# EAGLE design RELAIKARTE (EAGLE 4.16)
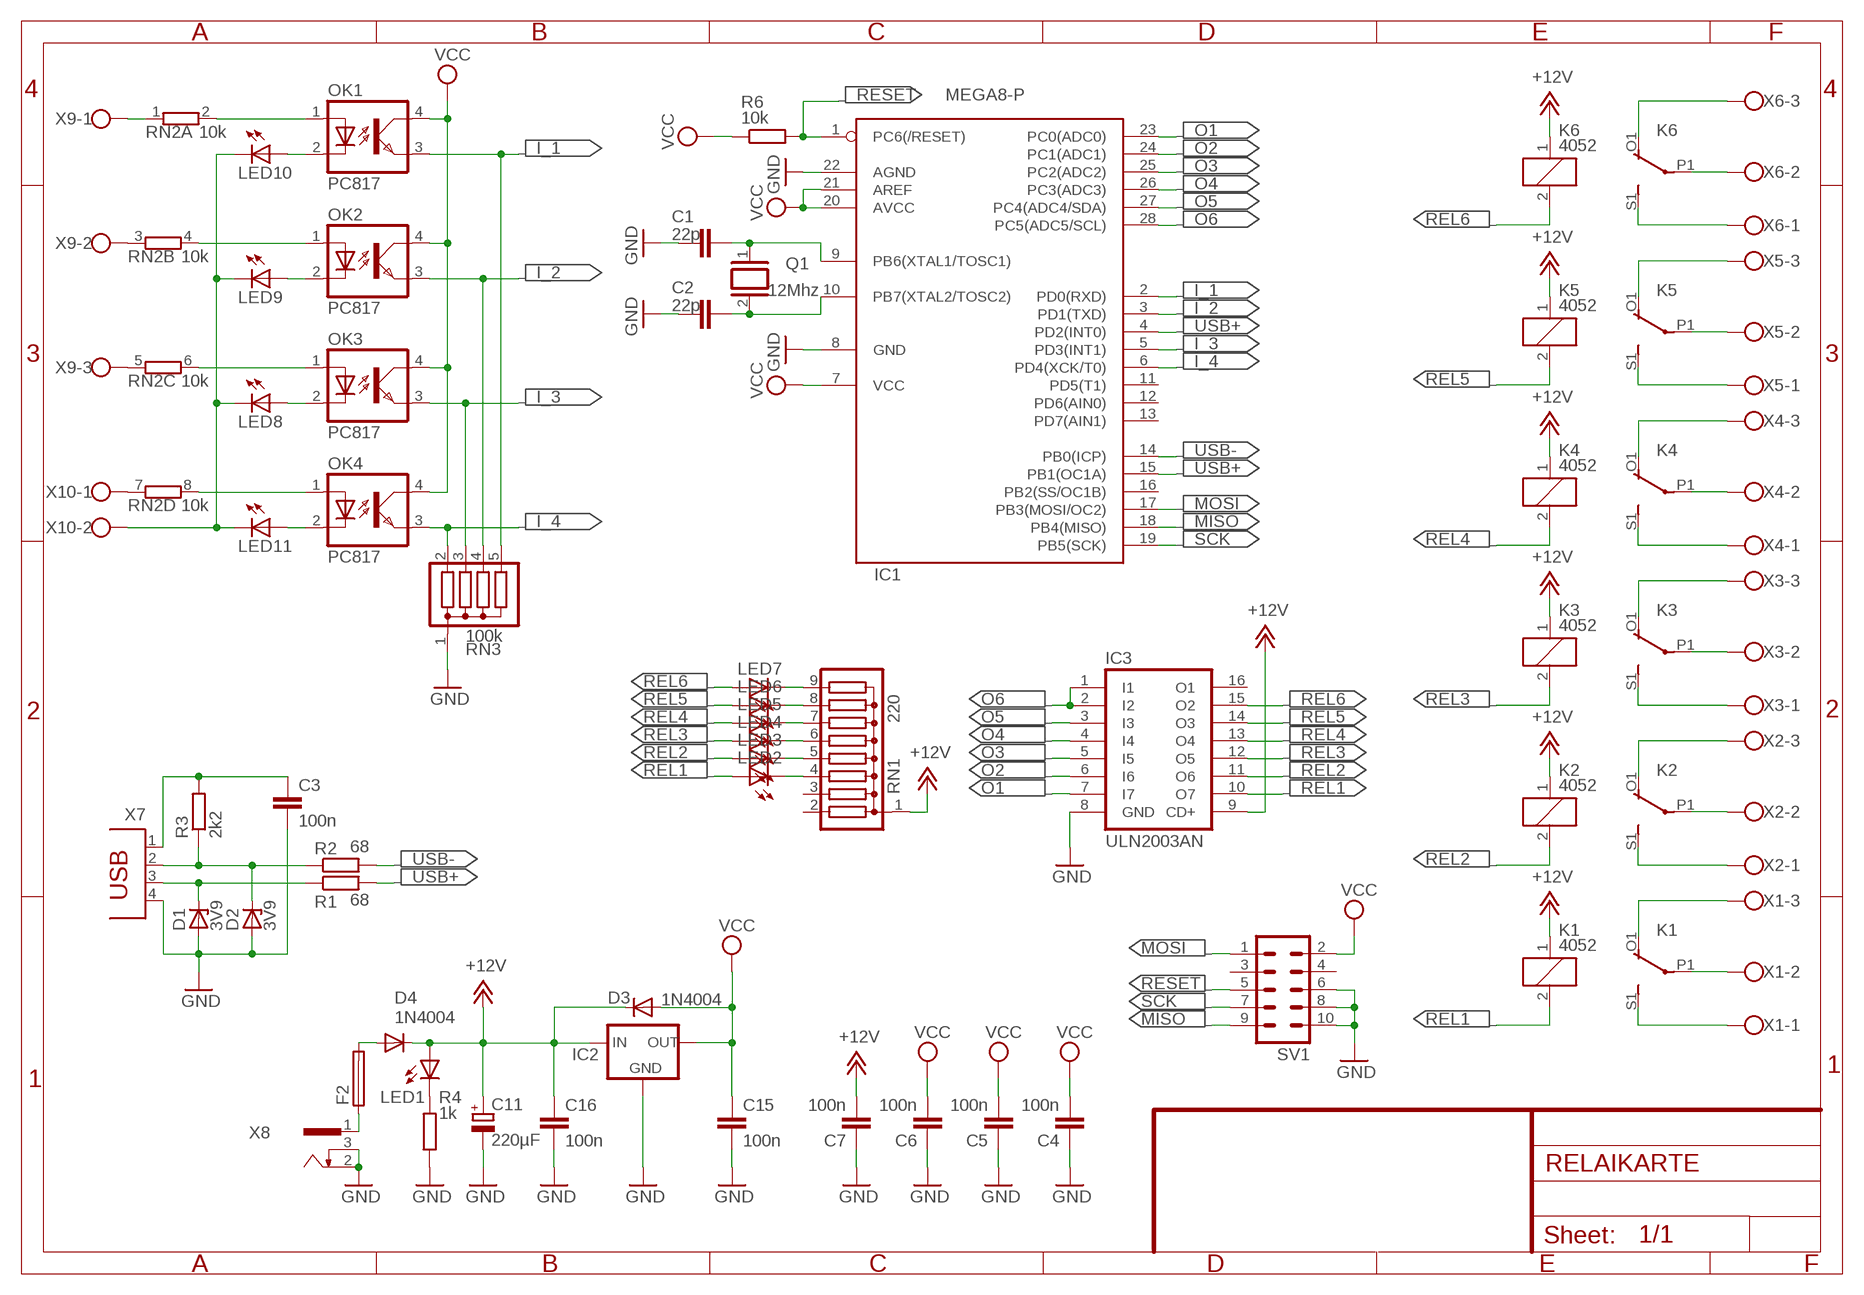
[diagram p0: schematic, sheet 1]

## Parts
C1  22p  C-EU025-024X044  [C025-024X044]
C2  22p  C-EU025-024X044  [C025-024X044]
C3  100n  C-EU050-024X044  [C050-024X044]
C4  100n  C-EU025-024X044  [C025-024X044]
C5  100n  C-EU025-024X044  [C025-024X044]
C6  100n  C-EU025-024X044  [C025-024X044]
C7  100n  C-EU025-024X044  [C025-024X044]
C11  220µF  CPOL-EUE3.5-8  [E3,5-8]
C15  100n  C-EU050-024X044  [C050-024X044]
C16  100n  C-EU050-024X044  [C050-024X044]
D1  3V9  BZX55  [DO35Z10]
D2  3V9  BZX55  [DO35Z10]
D3  1N4004  [DO41-10]
D4  1N4004  [DO41-10]
F2  PICOFUSE  [PICOFUSE]
IC1  MEGA8-P  [DIL28-3]
IC2  78XXS  [78XXS]
IC3  ULN2003AN  [DIL16]
K1  4052  [F4052]
K2  4052  [F4052]
K3  4052  [F4052]
K4  4052  [F4052]
K5  4052  [F4052]
K6  4052  [F4052]
LED1  LEDSQR2X5  [LED2X5]
LED2  LEDSQR2X5  [LED2X5]
LED3  LEDSQR2X5  [LED2X5]
LED4  LEDSQR2X5  [LED2X5]
LED5  LEDSQR2X5  [LED2X5]
LED6  LEDSQR2X5  [LED2X5]
LED7  LEDSQR2X5  [LED2X5]
LED8  LEDSQR2X5  [LED2X5]
LED9  LEDSQR2X5  [LED2X5]
LED10  LEDSQR2X5  [LED2X5]
LED11  LEDSQR2X5  [LED2X5]
OK1  PC817  [DIL04]
OK2  PC817  [DIL04]
OK3  PC817  [DIL04]
OK4  PC817  [DIL04]
Q1  12Mhz  XTAL/S  [QS]
R1  68  R-EU_0207/10  [0207/10]
R2  68  R-EU_0207/10  [0207/10]
R3  2k2  R-EU_0207/10  [0207/10]
R4  1k  R-EU_0207/10  [0207/10]
R6  10k  R-EU_0207/10  [0207/10]
RN1  220  G08R  [SIL9]
RN2  10k  E4R  [SIL8]
RN3  100k  G04R  [SIL5]
SV1  ML10  [ML10]
X1  W237-103  [W237-103]
X2  W237-103  [W237-103]
X3  W237-103  [W237-103]
X4  W237-103  [W237-103]
X5  W237-103  [W237-103]
X6  W237-103  [W237-103]
X7  PN61729  [PN61729]
X8  SCD-014A  [SCD-014-A]
X9  W237-3E  [W237-3E]
X10  W237-02P  [W237-132]

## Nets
+12V: C7.2 C11.+ C16.1 D3.C D4.C IC2.IN IC3.9(CD+) K1.1 K2.1 K3.1 K4.1 K5.1 K6.1 LED1.A RN1.1
GND: C1.1 C2.1 C3.2 C4.1 C5.1 C6.1 C7.1 C11.- C15.2 C16.2 D1.A D2.A IC1.8(GND) IC1.22(AGND) IC2.GND IC3.8(GND) R4.1 RN3.1 SV1.6 SV1.8 SV1.10 X7.4 X8.2 X8.3
I_1: IC1.2(PD0(RXD)) OK1.3(EMIT) RN3.5
I_2: IC1.3(PD1(TXD)) OK2.3(EMIT) RN3.4
I_3: IC1.5(PD3(INT1)) OK3.3(EMIT) RN3.3
I_4: IC1.6(PD4(XCK/T0)) OK4.3(EMIT) RN3.2
MISO: IC1.18(PB4(MISO)) SV1.9
MOSI: IC1.17(PB3(MOSI/OC2)) SV1.1
N$1: C1.2 IC1.9(PB6(XTAL1/TOSC1)) Q1.1
N$2: K5.P1(2:P) X5.2
N$3: K6.P1(2:P) X6.2
N$4: C2.2 IC1.10(PB7(XTAL2/TOSC2)) Q1.2
N$5: D1.C R1.1 X7.3
N$6: D2.C R2.1 R3.1 X7.2
N$7: C3.1 R3.2 X7.1
N$8: LED1.K(C) R4.2
N$9: K1.S1(2:S) X1.1
N$10: K1.O1(2:O) X1.3
N$11: K2.S1(2:S) X2.1
N$12: K2.O1(2:O) X2.3
N$13: K3.S1(2:S) X3.1
N$14: K3.O1(2:O) X3.3
N$15: K4.S1(2:S) X4.1
N$16: K4.O1(2:O) X4.3
N$17: K5.S1(2:S) X5.1
N$18: K5.O1(2:O) X5.3
N$19: K6.S1(2:S) X6.1
N$20: K6.O1(2:O) X6.3
N$21: D4.A F2.2
N$22: F2.1 X8.1
N$25: K1.P1(2:P) X1.2
N$27: K2.P1(2:P) X2.2
N$28: K3.P1(2:P) X3.2
N$29: K4.P1(2:P) X4.2
N$31: OK1.1(A) RN2.2
N$32: OK2.1(A) RN2.4
N$33: LED7.K(C) RN1.9
N$34: LED6.K(C) RN1.8
N$35: LED5.K(C) RN1.7
N$36: LED4.K(C) RN1.6
N$37: LED3.K(C) RN1.5
N$38: LED2.K(C) RN1.4
N$39: OK3.1(A) RN2.6
N$40: OK4.1(A) RN2.8
N$41: RN2.1 X9.1
N$42: RN2.3 X9.2
N$43: RN2.5 X9.3
N$44: RN2.7 X10.1
N$45: LED8.K(C) LED9.K(C) LED10.K(C) LED11.K(C) X10.2
N$46: LED10.A OK1.2(C)
N$47: LED9.A OK2.2(C)
N$48: LED8.A OK3.2(C)
N$49: LED11.A OK4.2(C)
O1: IC1.23(PC0(ADC0)) IC3.7(I7)
O2: IC1.24(PC1(ADC1)) IC3.6(I6)
O3: IC1.25(PC2(ADC2)) IC3.5(I5)
O4: IC1.26(PC3(ADC3)) IC3.4(I4)
O5: IC1.27(PC4(ADC4/SDA)) IC3.3(I3)
O6: IC1.28(PC5(ADC5/SCL)) IC3.1(I1) IC3.2(I2)
REL1: IC3.10(O7) K1.2 LED2.A
REL2: IC3.11(O6) K2.2 LED3.A
REL3: IC3.12(O5) K3.2 LED4.A
REL4: IC3.13(O4) K4.2 LED5.A
REL5: IC3.14(O3) K5.2 LED6.A
REL6: IC3.15(O2) K6.2 LED7.A
RESET: IC1.1(PC6(/RESET)) R6.2 SV1.5
SCK: IC1.19(PB5(SCK)) SV1.7
USB+: IC1.4(PD2(INT0)) IC1.15(PB1(OC1A)) R1.2
USB-: IC1.14(PB0(ICP)) R2.2
VCC: C4.2 C5.2 C6.2 C15.1 D3.A IC1.7(VCC) IC1.20(AVCC) IC1.21(AREF) IC2.OUT OK1.4(COL) OK2.4(COL) OK3.4(COL) OK4.4(COL) R6.1 SV1.2
Unconnected: IC1.11(PD5(T1)) IC1.12(PD6(AIN0)) IC1.13(PD7(AIN1)) IC1.16(PB2(SS/OC1B)) IC3.16(O1) K1.O2(3:O) K1.P2(3:P) K1.S2(3:S) K2.O2(3:O) K2.P2(3:P) K2.S2(3:S) K3.O2(3:O) K3.P2(3:P) K3.S2(3:S) K4.O2(3:O) K4.P2(3:P) K4.S2(3:S) K5.O2(3:O) K5.P2(3:P) K5.S2(3:S) K6.O2(3:O) K6.P2(3:P) K6.S2(3:S) RN1.2 RN1.3 SV1.3 SV1.4

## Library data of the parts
C1-C7 C15 C16 = rcl:C-EU: CAPACITOR, European symbol
C11 = rcl:CPOL-EU: POLARIZED CAPACITOR, European symbol
D1 D2 = diode:BZX55: Z DIODE
D3 D4 = diode:1N4004: DIODE
F2 = fuse:PICOFUSE: PICOFUSE
IC1 = avr-1:MEGA8-P: MICROCONTROLLER 8 Kbytes FLASH 1 kbytes SRAM 512 bytes EEPROM USART 4-channel 10 bit ADC 2-channel 8 bit ADC
IC2 = v-reg:78XXS: VOLTAGE REGULATOR
IC3 = uln-udn:ULN2003A: DRIVER ARRAY
K1-K6 = relay:4052: RELAY 2 x switch, Finder
LED1-LED11 = led:LED: LED
OK1-OK4 = optocoupler:PC817: SHARP OPTO COUPLER
Q1 = special:XTAL/S: CRYSTAL
R1-R4 R6 = rcl:R-EU_: RESISTOR, European symbol
RN1 = resistor-sil:G08R: SIL RESISTOR
RN2 = resistor-sil:E4R: SIL RESISTOR
RN3 = resistor-sil:G04R: SIL RESISTOR
SV1 = con-harting-ml:ML10: HARTING
X1-X6 = con-wago-500:W237-103: WAGO SCREW CLAMP
X7 = con-berg:PN61729: BERG USB connector
X8 = con-shiua-chyuan:SCD-014A: Power Jack 2.5mm
X9 = con-wago-508:W237-3E: WAGO SREW CLAMP
X10 = con-wago-508:W237-02P: WAGO SREW CLAMP

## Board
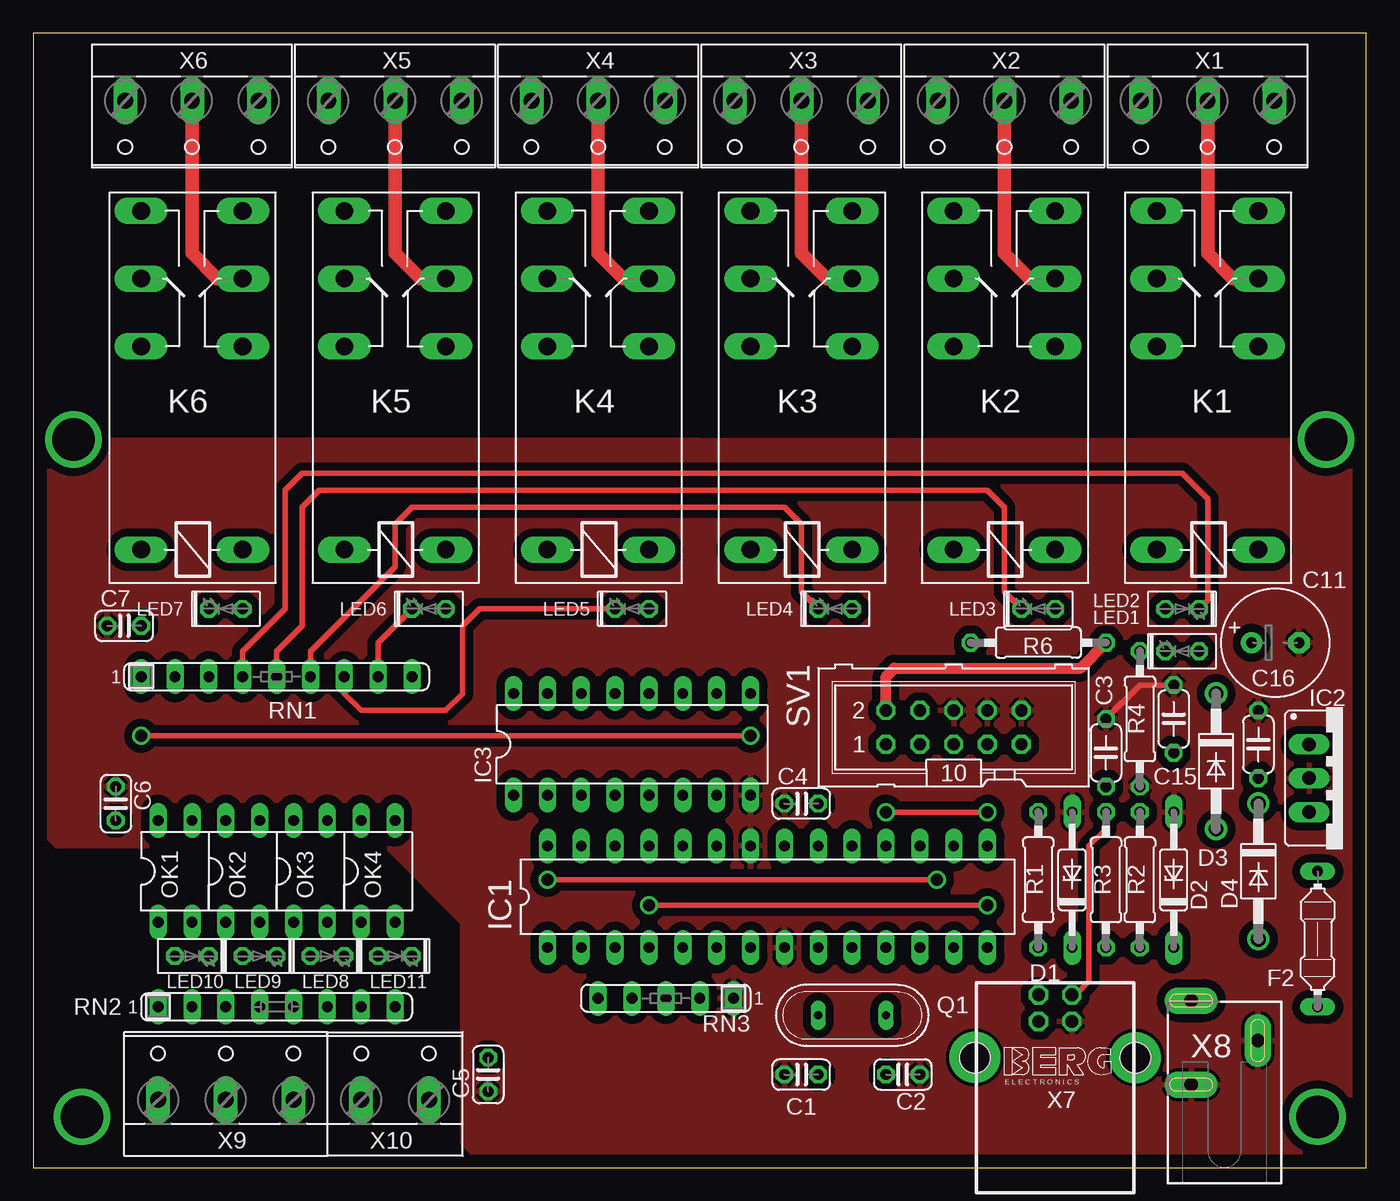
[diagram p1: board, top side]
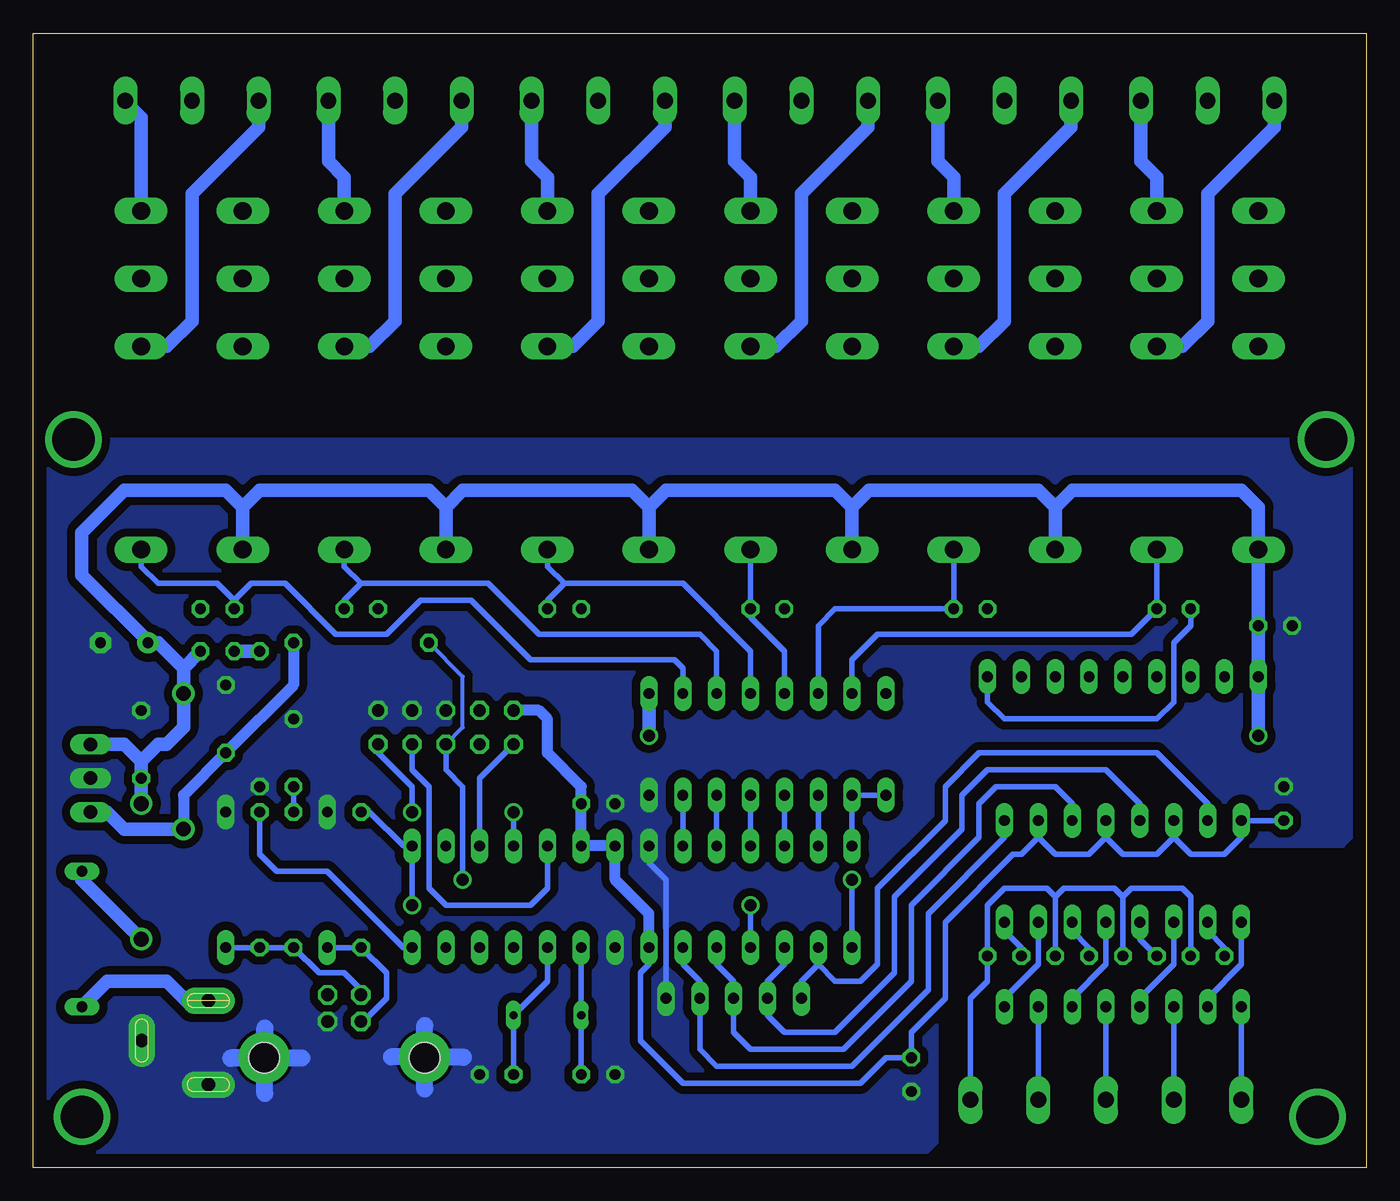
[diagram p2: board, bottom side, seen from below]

Size 100 x 85.07 mm. Coordinates in mm from the lower left corner, seen from the top.
Outline: 100,0 100,85.07 0,85.07 0,0 100,0
Copper layers (1*16): Top 0.035mm / dielectric 1.5mm / Bottom 0.035mm
Design rules "default": minimum track width 10mil, minimum drill 24mil, track to track 8mil, track to pad 8mil, pad to pad 8mil, via to via 8mil, smd to smd 8mil, copper to edge 40mil, drill to drill 8mil, minimum pad ring 10mil, minimum via ring 8mil, stop-mask expansion 4mil, vias tented up to drill 0mil, thermal gap 10mil

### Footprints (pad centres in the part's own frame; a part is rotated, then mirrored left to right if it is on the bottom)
C025-024X044 = drill 0.813 octagon: 1 -1.27,0; 2 1.27,0
C050-024X044 = drill 0.813 octagon: 1 -2.54,0; 2 2.54,0
E3,5-8 = drill 0.813 pad 1.6 round: + -1.778,0 | drill 0.813 pad 1.6 octagon: - 1.778,0
DO35Z10 = drill 0.813 long: A 5.08,0; C -5.08,0
DO41-10 = drill 1.118 round: A 5.08,0; C -5.08,0
PICOFUSE = drill 0.813 long: 1 -5.08,0; 2 5.08,0
DIL28-3 = drill 0.813 long: 1 -16.51,-3.81; 2 -13.97,-3.81; 3 -11.43,-3.81; 4 -8.89,-3.81; 5 -6.35,-3.81; 6 -3.81,-3.81; 7 -1.27,-3.81; 8 1.27,-3.81; 9 3.81,-3.81; 10 6.35,-3.81; 11 8.89,-3.81; 12 11.43,-3.81; 13 13.97,-3.81; 14 16.51,-3.81; 15 16.51,3.81; 16 13.97,3.81; 17 11.43,3.81; 18 8.89,3.81; 19 6.35,3.81; 20 3.81,3.81; 21 1.27,3.81; 22 -1.27,3.81; 23 -3.81,3.81; 24 -6.35,3.81; 25 -8.89,3.81; 26 -11.43,3.81; 27 -13.97,3.81; 28 -16.51,3.81
78XXS = drill 1.016 long: GND 0,-2.54; IN -2.54,-2.54; OUT 2.54,-2.54
DIL16 = drill 0.813 long: 1 -8.89,-3.81; 2 -6.35,-3.81; 3 -3.81,-3.81; 4 -1.27,-3.81; 5 1.27,-3.81; 6 3.81,-3.81; 7 6.35,-3.81; 8 8.89,-3.81; 9 8.89,3.81; 10 6.35,3.81; 11 3.81,3.81; 12 1.27,3.81; 13 -1.27,3.81; 14 -3.81,3.81; 15 -6.35,3.81; 16 -8.89,3.81
F4052 = drill 1.321 long: 1 -3.81,3.81; 2 -3.81,-3.81; O1 11.43,-3.81; O2 11.43,3.81; P1 16.51,-3.81; P2 16.51,3.81; S1 21.59,-3.81; S2 21.59,3.81
LED2X5 = drill 0.813 octagon: A -1.27,0; K 1.27,0
DIL04 = drill 0.813 long: 1 -1.27,-3.81; 2 1.27,-3.81; 3 1.27,3.81; 4 -1.27,3.81
QS = drill 0.61 long: 1 -2.54,0; 2 2.54,0
0207/10 = drill 0.813 octagon: 1 -5.08,0; 2 5.08,0
SIL9 = drill 0.813 long: 1 -10.16,0; 2 -7.62,0; 3 -5.08,0; 4 -2.54,0; 5 0,0; 6 2.54,0; 7 5.08,0; 8 7.62,0; 9 10.16,0
SIL8 = drill 0.813 long: 1 -8.89,0; 2 -6.35,0; 3 -3.81,0; 4 -1.27,0; 5 1.27,0; 6 3.81,0; 7 6.35,0; 8 8.89,0
SIL5 = drill 0.813 long: 1 -5.08,0; 2 -2.54,0; 3 0,0; 4 2.54,0; 5 5.08,0
ML10 = drill 0.914 octagon: 1 -5.08,-1.27; 2 -5.08,1.27; 3 -2.54,-1.27; 4 -2.54,1.27; 5 0,-1.27; 6 0,1.27; 7 2.54,-1.27; 8 2.54,1.27; 9 5.08,-1.27; 10 5.08,1.27
W237-103 = drill 1.194 long: 1 -5,-1.29; 2 0,-1.29; 3 5,-1.29
PN61729 = drill 0.95 octagon: 1 1.25,4.71; 2 -1.25,4.71; 3 -1.25,2.71; 4 1.25,2.71 | hole 2.3: -6.02,0; 6.02,0
SCD-014-A = drill 1 pad 2 long: 1 -2.5,13.8; 2 -2.5,7.5; 3 2.5,10.8
W237-3E = drill 1.194 long: 1 -5.08,-0.635; 2 0,-0.635; 3 5.08,-0.635
W237-132 = drill 1.194 long: 1 -2.54,-0.635; 2 2.54,-0.635

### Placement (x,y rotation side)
C1  57.62,6.98 0 top
C2  65.24,6.98 180 top
C3  80.48,31.11 90 top
C4  57.62,27.3 0 top
C5  34.12,6.98 90 top
C6  6.18,27.3 270 top
C7  6.82,40.63 0 top
C11  93.18,39.36 0 top
C15  85.56,33.65 90 top
C16  91.91,31.75 90 top
D1  77.94,21.59 90 top
D2  85.56,21.59 90 top
D3  88.73,30.48 270 top
D4  91.91,22.22 270 top
F2  96.35,17.14 90 top
IC1  55.08,20.32 0 top
IC2  98.26,29.21 270 top
IC3  44.92,31.75 0 top
K1  88.1,50.16 90 top
K2  72.86,50.16 90 top
K3  57.62,50.16 90 top
K4  42.38,50.16 90 top
K5  27.14,50.16 90 top
K6  11.9,50.16 90 top
LED1  86.19,38.73 180 top
LED2  86.19,41.9 0 top
LED3  75.4,41.9 180 top
LED4  60.16,41.9 180 top
LED5  44.92,41.9 180 top
LED6  29.68,41.9 180 top
LED7  14.44,41.9 180 top
LED8  22.06,15.87 0 top
LED9  16.98,15.87 0 top
LED10  11.9,15.87 0 top
LED11  27.14,15.87 0 top
OK1  10.63,22.22 0 top
OK2  15.71,22.22 0 top
OK3  20.79,22.22 0 top
OK4  25.87,22.22 0 top
Q1  61.43,11.42 0 top
R1  75.4,21.59 90 top
R2  83.02,21.59 90 top
R3  80.48,21.59 90 top
R4  83.02,33.65 90 top
R6  75.4,39.36 180 top
RN1  18.25,36.82 0 top
RN2  18.25,12.06 0 top
RN3  47.46,12.69 180 top
SV1  69.05,33.02 0 top
X1  88.1,78.73 180 top
X2  72.86,78.73 180 top
X3  57.62,78.73 180 top
X4  42.38,78.73 180 top
X5  27.14,78.73 180 top
X6  11.9,78.73 180 top
X7  76.67,8.25 0 top
X8  89.37,-1.27 0 top
X9  14.44,5.71 0 top
X10  27.14,5.71 0 top

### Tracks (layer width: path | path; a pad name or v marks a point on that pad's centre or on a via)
+12V  (via drill 0.9)
  Top 0.406: v8.09,32.38 v53.81,32.38
  Bottom 0.406: 91.27,39.36 C11.+
  Bottom 1.016: 84.29,49.52 83.02,50.79 70.32,50.79 69.05,49.52 | 69.05,49.52 K2.1 | 69.05,49.52 67.78,50.79 55.08,50.79 53.81,49.52 | 53.81,49.52 K3.1 | 53.81,49.52 52.54,50.79 39.84,50.79 38.57,49.52 | 38.57,49.52 K4.1 | 38.57,49.52 37.3,50.79 24.6,50.79 23.33,49.52 | 23.33,49.52 K5.1 | 23.33,49.52 22.06,50.79 9.36,50.79 8.09,49.52 K6.1 C7.2 RN1.1 v8.09,32.38 | v53.81,32.38 IC3.9 | 84.29,49.52 K1.1 | 84.29,49.52 85.56,50.79 93.18,50.79 96.35,47.62 96.35,44.45 91.27,39.36 90.64,39.36 88.73,37.46 | D4.C C16.1 91.91,30.48 | 91.91,30.48 93.18,31.75 IC2.IN | 91.91,30.48 90.64,31.75 90,31.75 88.73,33.02 D3.C 88.73,37.46 | 88.73,37.46 LED1.A
GND  (via drill 2.2 pad 3.81)
  Top 0.406: C15.2 83.02,36.19 C3.2
  Bottom 0.406: RN3.1 52.54,21.59 53.81,22.86 IC1.22
  Bottom 1.27: v70.65,8.27 67.76,8.27 67.76,8.31 70.64,8.31 | 70.64,8.31 73.15,8.31 | 70.64,8.31 70.64,10.64 | 70.64,5.89 70.64,8.31 | v82.68,8.23 85.17,8.23 85.17,8.2 85.14,8.23 82.63,8.23 | 82.63,8.23 79.86,8.23 | 82.63,8.23 82.63,10.47 82.63,10.46 82.63,5.57
  pour Bottom (isolate 0.61, no thermals): 0.47,25.39 0.47,54.6 99.53,54.6 99.53,0.63 33.49,0.63 32.22,1.9 32.22,18.41 26.51,24.12 1.74,24.12
  pour Top (isolate 0.61): 0.47,54.6 99.5,54.51 99.5,0.54 33.49,0.63 32.22,1.9 32.22,18.41 26.51,24.12 1.74,24.12 0.47,25.39
I_1
  Bottom 0.406: 41.11,15.23 42.38,13.96 RN3.5 | 41.11,15.23 IC1.2 | 41.11,15.23 39.84,13.96 37.94,13.96 36.66,15.23 36.66,20.95 31.59,26.03 31.59,28.57 29.05,31.11 15.71,31.11 11.9,27.3 OK1.3
I_2
  Bottom 0.406: IC1.3 43.65,15.23 44.92,13.96 RN3.4 44.92,11.42 43.65,10.15 39.84,10.15 35.4,14.6 35.4,20.32 30.32,25.39 30.32,27.94 28.41,29.84 19.52,29.84 16.98,27.3 OK2.3
I_3
  Bottom 0.406: IC1.5 48.73,15.23 47.46,13.96 | 47.46,13.96 RN3.3 | 47.46,13.96 47.46,10.15 46.19,8.88 39.2,8.88 34.12,13.96 34.12,19.68 29.05,24.76 29.05,27.3 27.78,28.57 23.33,28.57 22.06,27.3 OK3.3
I_4
  Bottom 0.406: IC1.6 51.27,15.23 50,13.96 RN3.2 50,8.88 48.73,7.62 38.57,7.62 32.86,13.33 32.86,19.05 27.14,24.76 OK4.3
MISO  (via drill 0.9)
  Top 0.406: v63.97,26.67 v71.59,26.67
  Bottom 0.406: IC1.18 v63.97,26.67 | v71.59,26.67 71.59,28.57 74.13,31.11 SV1.9
MOSI
  Bottom 0.406: IC1.17 66.51,29.21 SV1.1
N$1
  Bottom 0.406: IC1.9 Q1.1 C1.2
N$2
  Top 1.016: X5.2 27.14,68.58 29.05,66.67 K5.P1
N$3
  Top 1.016: X6.2 11.9,68.58 13.81,66.67 K6.P1
N$4
  Bottom 0.406: IC1.10 61.43,13.96 Q1.2 C2.2
N$5
  Bottom 0.406: X7.3 75.23,10.96 73.49,12.69 73.49,14.6 R1.1 D1.C
N$6
  Bottom 0.406: D2.C R2.1 R3.1 78.57,14.6 76.67,14.6 75.42,13.35 X7.2
N$7
  Top 0.406: 79.21,24.12 79.19,22.2 | 79.21,24.12 80.48,25.39 R3.2 | X7.1 78.2,12.96 79.21,13.96 79.21,24.12
  Bottom 0.406: R3.2 C3.1
N$8
  Bottom 1.016: R4.2 LED1.K
N$9
  Bottom 1.016: X1.1 93.1,79.93 91.91,78.73 K1.S1
N$10
  Bottom 1.016: X1.3 83.1,78.02 88.1,73.02 88.1,63.49 90,61.59 K1.O1
N$11
  Bottom 1.016: X2.1 77.86,75.48 76.67,74.29 K2.S1
N$12
  Bottom 1.016: X2.3 67.86,78.02 72.86,73.02 72.86,63.49 74.77,61.59 K2.O1
N$13
  Bottom 1.016: X3.1 62.62,75.48 61.43,74.29 K3.S1
N$14
  Bottom 1.016: X3.3 52.62,78.02 57.62,73.02 57.62,63.49 59.52,61.59 K3.O1
N$15
  Bottom 1.016: X4.1 47.38,75.48 46.19,74.29 K4.S1
N$16
  Bottom 1.016: X4.3 37.38,78.02 42.38,73.02 42.38,63.49 44.29,61.59 K4.O1
N$17
  Bottom 1.016: X5.1 32.14,75.48 30.95,74.29 K5.S1
N$18
  Bottom 1.016: X5.3 22.14,78.02 27.14,73.02 27.14,63.49 29.05,61.59 K5.O1
N$19
  Bottom 1.016: X6.1 16.9,75.48 15.71,74.29 K6.S1
N$20
  Bottom 1.016: X6.3 6.9,78.02 11.9,73.02 11.9,63.49 13.81,61.59 K6.O1
N$21
  Bottom 1.016: D4.A 96.35,21.59 F2.2
N$22
  Bottom 1.016: X8.1 87.33,12.06 88.1,12.06 90,13.96 94.45,13.96 F2.1
N$23  (via drill 3.2)
  other vias: 96.99,54.6
N$24  (via drill 3.2)
  other vias: 3.01,54.6
N$25
  Top 1.016: X1.2 88.1,68.58 90,66.67 K1.P1
N$26  (via drill 3.2)
  other vias: 3.65,3.81
N$27
  Top 1.016: X2.2 72.86,68.58 74.77,66.67 K2.P1
N$28
  Top 1.016: X3.2 57.62,68.58 59.52,66.67 K3.P1
N$29
  Top 1.016: X4.2 42.38,68.58 44.29,66.67 K4.P1
N$30  (via drill 3.2)
  other vias: 96.35,3.81
N$31
  Bottom 0.406: OK1.1 9.36,15.23 11.9,12.69 RN2.2
N$32
  Bottom 0.406: OK2.1 14.44,15.23 16.98,12.69 RN2.4
N$33
  Bottom 0.406: LED7.K 13.17,40.63 14.44,39.36 14.44,34.92 15.71,33.65 27.14,33.65 28.41,34.92 RN1.9
N$34
  Top 0.406: RN1.8 25.87,39.36 LED6.K
N$35
  Top 0.406: RN1.7 23.33,35.55 24.6,34.28 30.95,34.28 32.22,35.55 32.22,40.63 33.49,41.9 LED5.K
N$36
  Top 0.406: RN1.6 20.79,38.73 27.14,45.08 27.14,48.25 28.41,49.52 56.35,49.52 57.62,48.25 57.62,43.17 LED4.K
N$37
  Top 0.406: RN1.5 18.25,38.73 20.16,40.63 20.16,49.52 21.43,50.79 71.59,50.79 72.86,49.52 72.86,43.17 LED3.K
N$38
  Top 0.406: RN1.4 15.71,38.73 18.89,41.9 18.89,50.79 20.16,52.06 86.19,52.06 88.1,50.16 88.1,42.54 LED2.K
N$39
  Bottom 0.406: OK3.1 19.52,15.23 22.06,12.69 RN2.6
N$40
  Bottom 0.406: OK4.1 24.6,15.23 27.14,12.69 RN2.8
N$41
  Bottom 0.406: X9.1 RN2.1
N$42
  Bottom 0.406: X9.2 RN2.3
N$43
  Bottom 0.406: X9.3 RN2.5
N$44
  Bottom 0.406: X10.1 RN2.7
N$45
  Bottom 0.406: LED10.K 13.17,20.32 13.81,20.95 17.62,20.95 18.25,20.32 | 18.25,20.32 LED9.K | 18.25,20.32 18.89,20.95 22.7,20.95 23.33,20.32 | 23.33,20.32 LED8.K | 23.33,20.32 23.96,20.95 27.14,20.95 28.41,19.68 LED11.K 28.41,13.96 29.68,12.69 X10.2
N$46
  Bottom 0.406: LED10.A 10.63,16.51 11.9,17.78 OK1.2
N$47
  Bottom 0.406: LED9.A 16.98,17.14 OK2.2
N$48
  Bottom 0.406: LED8.A 20.79,16.51 22.06,17.78 OK3.2
N$49
  Bottom 0.406: LED11.A 25.87,16.51 27.14,17.78 OK4.2
O1
  Bottom 0.406: IC1.23 IC3.7
O2
  Bottom 0.406: IC1.24 IC3.6
O3
  Bottom 0.406: IC1.25 IC3.5
O4
  Bottom 0.406: IC1.26 IC3.4
O5
  Bottom 0.406: IC1.27 IC3.3
O6
  Bottom 0.406: IC1.28 IC3.2 IC3.1
REL1
  Bottom 0.406: IC3.10 51.27,37.46 51.91,38.09 62.7,38.09 67.14,42.54 70.95,42.54 73.49,40 77.3,40 81.11,43.81 83.65,43.81 84.92,42.54 | K1.2 91.91,45.08 90.64,43.81 86.19,43.81 84.92,42.54 | 84.92,42.54 LED2.A
REL2
  Bottom 0.406: IC3.11 48.73,38.73 50,40 62.06,40 65.88,43.81 75.4,43.81 | 75.4,43.81 76.67,42.54 LED3.A | K2.2 76.67,45.08 75.4,43.81
REL3
  Bottom 0.406: IC3.12 46.19,38.73 51.27,43.81 60.16,43.81 | 60.16,43.81 61.43,42.54 LED4.A | K3.2 61.43,45.08 60.16,43.81
REL4
  Bottom 0.406: IC3.13 43.65,38.73 46.19,41.27 LED5.A K4.2
REL5
  Bottom 0.406: IC3.14 41.11,40.63 39.84,41.9 LED6.A K5.2
REL6
  Bottom 0.406: K6.2 LED7.A 17.62,40 36.66,40 38.57,38.09 IC3.15
RESET  (via drill 0.9)
  Top 0.406: v38.57,21.59 v67.78,21.59
  Bottom 0.305: SV1.5 67.78,33.02 67.78,36.82 R6.2
  Bottom 0.406: SV1.5 69.05,29.84 67.78,28.57 v67.78,21.59 | IC1.1 v38.57,21.59
SCK
  Bottom 0.406: SV1.7 71.59,29.84 70.32,28.57 70.32,20.95 69.05,19.68 62.7,19.68 61.43,20.95 IC1.19
USB+  (via drill 0.9)
  Top 0.406: v46.19,19.68 v71.59,19.68
  Bottom 0.406: IC1.4 v46.19,19.68 | v71.59,19.68 IC1.15 72.22,24.12 74.77,26.67 R1.2
USB-
  Bottom 0.406: IC1.14 72.22,16.51 77.94,22.22 81.75,22.22 83.02,23.49 R2.2
VCC
  Top 0.813: SV1.2 63.97,36.82 64.6,37.46 78.57,37.46 R6.1
  Bottom 0.406: 14.44,24.76 13.17,23.49 10.63,23.49 9.36,24.76 OK1.4 C6.2 | 14.44,24.76 OK2.4 | 14.44,24.76 15.71,23.49 18.25,23.49 19.52,24.76 | 19.52,24.76 OK3.4 | 19.52,24.76 20.79,23.49 23.33,23.49 24.6,24.76 | 24.6,24.76 OK4.4 | 24.6,24.76 25.87,23.49 26.51,23.49 31.59,18.41 31.59,12.69 34.12,10.15 C5.2 36.03,8.25 37.94,6.34 51.27,6.34 54.45,9.52 54.45,14.6 53.81,15.23 IC1.7
  Bottom 0.813: SV1.2 62.06,34.28 61.43,33.65 61.43,31.11 58.89,28.57 C4.2 IC1.20 IC1.21 56.35,21.59 53.81,19.05 IC1.7 | R6.1 80.48,36.19 C15.1 88.73,27.94 D3.A
  Bottom 1.016: D3.A 93.18,25.39 94.45,26.67 IC2.OUT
